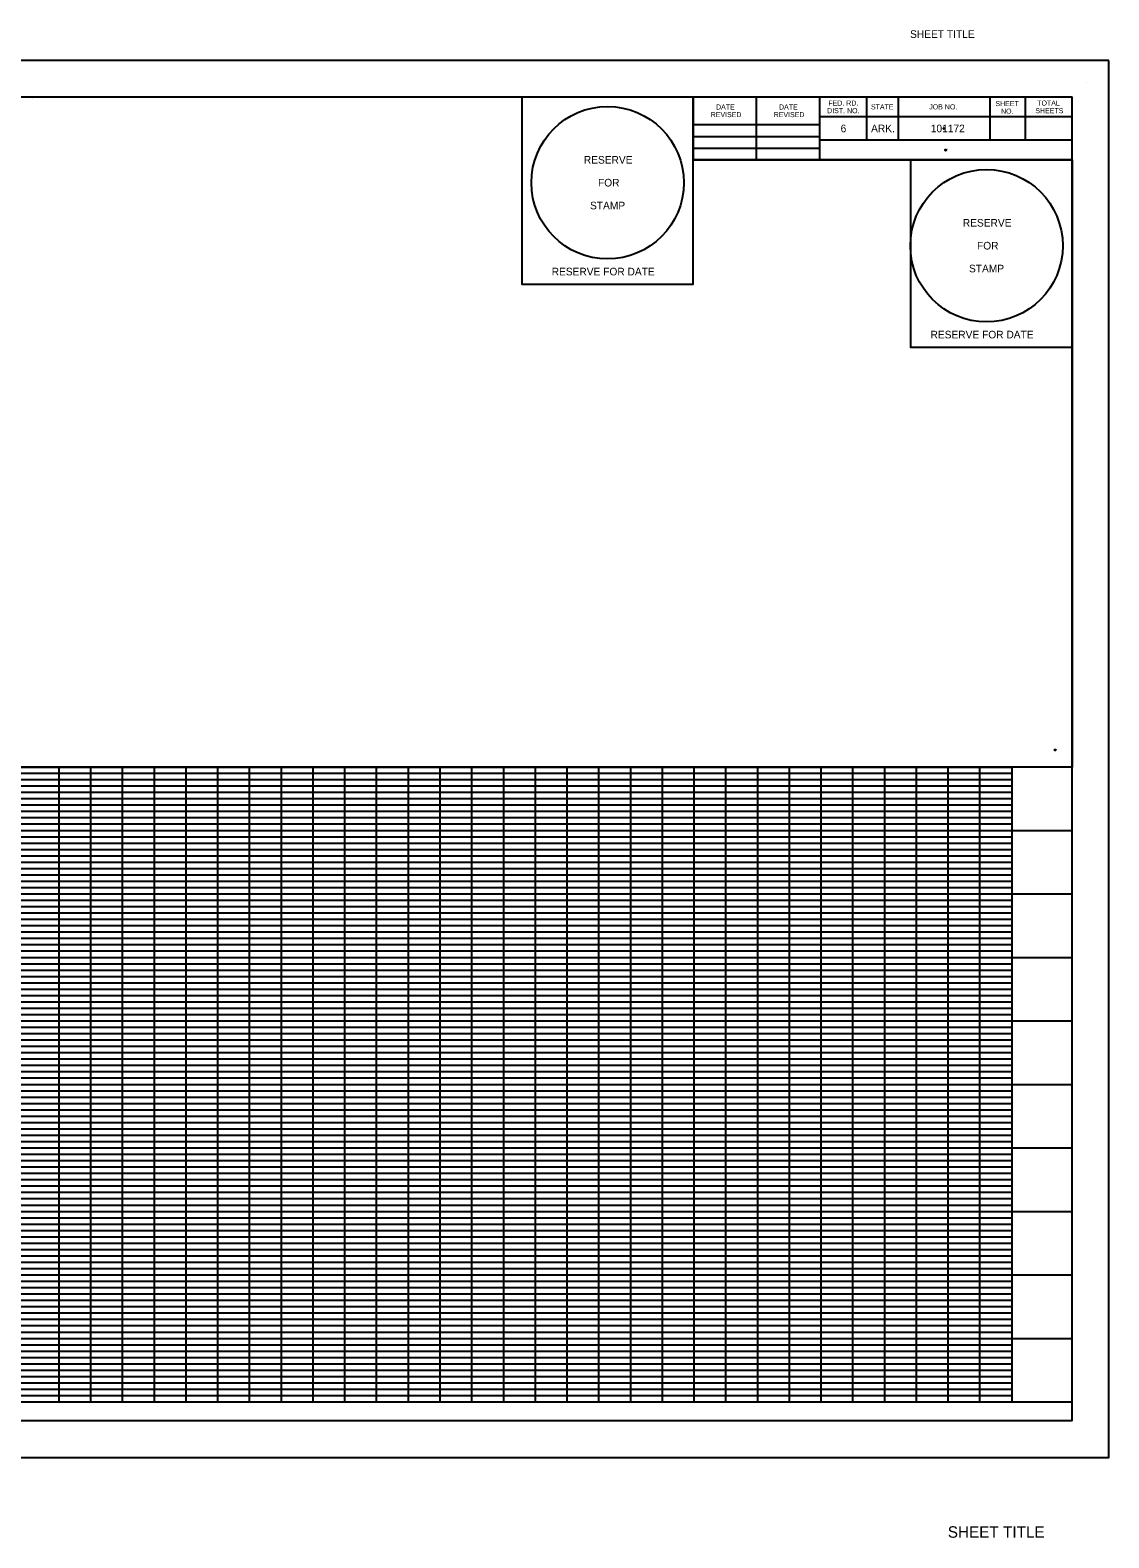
# Model space of a CAD drawing. Extents: x 0 to 17, y -0.6 to 11.2.
# Drawn here: x 8.51 to 17, y -0.63 to 11.24 of the extents above; entities that cross this region are included whole.
import ezdxf

# ---------------------------------------------------------------- set-up
doc = ezdxf.new("R2010")
doc.units = 0
for name, color, linetype in [('G-ANNO-TEXT', 7, 'Continuous'), ('G-Border-Paper', 7, 'Continuous'), ('G-Border-Sheet', 7, 'Continuous'), ('G-Grid-Border', 7, 'Continuous'), ('G-Grid-Major', 7, 'Continuous'), ('G-Grid-Minor', 7, 'Continuous'), ('G-No Plot-Anchor', 7, 'Continuous'), ('G-No Plot-Border-1', 7, 'Continuous'), ('G-No Plot-Border-2', 7, 'Continuous'), ('G-No Plot-Stamp-1', 7, 'Continuous'), ('G-No Plot-Stamp-2', 7, 'Continuous'), ('G-Table-Major', 7, 'Continuous'), ('G-Table-Minor', 7, 'Continuous')]:
    doc.layers.add(name, color=color, linetype=linetype)

msp = doc.modelspace()

# ---------------------------------------------------------------- linework, layer by layer
at = {"layer": 'G-ANNO-TEXT'}
msp.add_line((16.821, 10.827), (16.821, 10.827), dxfattribs=at)
at = {"layer": 'G-Border-Paper'}
msp.add_lwpolyline([(17, 11), (0, 11), (0, 0), (17, 0)], close=True, dxfattribs=at)
at = {"layer": 'G-Border-Sheet'}
for p, q in [((0.758, 10.712), (16.712, 10.712)), ((16.712, 0.288), (16.712, 10.712)), ((16.712, 0.288), (0.758, 0.288))]:
    msp.add_line(p, q, dxfattribs=at)
at = {"layer": 'G-Grid-Border'}
for p, q in [((16.712, 5.435), (0.758, 5.435)), ((16.712, 0.435), (0.758, 0.435))]:
    msp.add_line(p, q, dxfattribs=at)
msp.add_lwpolyline([(1.235, 5.435), (16.235, 5.435), (16.235, 0.435), (1.235, 0.435)], close=True, dxfattribs=at)
at = {"layer": 'G-Grid-Major'}
for p, q in [((8.735, 0.435), (8.735, 5.435)), ((9.235, 0.435), (9.235, 5.435)), ((9.735, 0.435), (9.735, 5.435)), ((10.235, 0.435), (10.235, 5.435)), ((10.735, 0.435), (10.735, 5.435)), ((11.235, 0.435), (11.235, 5.435)), ((11.735, 0.435), (11.735, 5.435)), ((12.235, 0.435), (12.235, 5.435)), ((12.735, 0.435), (12.735, 5.435)), ((13.235, 0.435), (13.235, 5.435)), ((13.735, 0.435), (13.735, 5.435)), ((14.235, 0.435), (14.235, 5.435)), ((14.735, 0.435), (14.735, 5.435)), ((15.235, 0.435), (15.235, 5.435)), ((15.735, 0.435), (15.735, 5.435)), ((16.712, 4.935), (0.758, 4.935)), ((16.712, 4.435), (0.758, 4.435)), ((16.712, 3.935), (0.758, 3.935)), ((16.712, 3.435), (0.758, 3.435)), ((16.712, 2.935), (0.758, 2.935)), ((16.712, 2.435), (0.758, 2.435)), ((16.712, 1.935), (0.758, 1.935)), ((16.712, 1.435), (0.758, 1.435)), ((16.712, 0.935), (0.758, 0.935))]:
    msp.add_line(p, q, dxfattribs=at)
msp.add_lwpolyline([(1.235, 5.435), (16.235, 5.435), (16.235, 0.435), (1.235, 0.435)], close=True, dxfattribs=at)
at = {"layer": 'G-Grid-Minor'}
for p, q in [((16.235, 5.385), (1.235, 5.385)), ((8.985, 0.435), (8.985, 5.435)), ((9.485, 0.435), (9.485, 5.435)), ((9.985, 0.435), (9.985, 5.435)), ((10.485, 0.435), (10.485, 5.435)), ((10.985, 0.435), (10.985, 5.435)), ((11.485, 0.435), (11.485, 5.435)), ((11.985, 0.435), (11.985, 5.435)), ((12.485, 0.435), (12.485, 5.435)), ((12.985, 0.435), (12.985, 5.435)), ((13.485, 0.435), (13.485, 5.435)), ((13.985, 0.435), (13.985, 5.435)), ((14.485, 0.435), (14.485, 5.435)), ((14.985, 0.435), (14.985, 5.435)), ((15.485, 0.435), (15.485, 5.435)), ((15.985, 0.435), (15.985, 5.435)), ((16.235, 5.335), (1.235, 5.335)), ((16.235, 5.285), (1.235, 5.285)), ((16.235, 5.235), (1.235, 5.235)), ((16.235, 5.185), (1.235, 5.185)), ((16.235, 5.135), (1.235, 5.135)), ((16.235, 5.085), (1.235, 5.085)), ((16.235, 5.035), (1.235, 5.035)), ((16.235, 4.985), (1.235, 4.985)), ((16.235, 4.885), (1.235, 4.885)), ((16.235, 4.835), (1.235, 4.835)), ((16.235, 4.785), (1.235, 4.785)), ((16.235, 4.735), (1.235, 4.735)), ((16.235, 4.685), (1.235, 4.685)), ((16.235, 4.635), (1.235, 4.635)), ((16.235, 4.585), (1.235, 4.585)), ((16.235, 4.535), (1.235, 4.535)), ((16.235, 4.485), (1.235, 4.485)), ((16.235, 4.385), (1.235, 4.385)), ((16.235, 4.335), (1.235, 4.335)), ((16.235, 4.285), (1.235, 4.285)), ((16.235, 4.235), (1.235, 4.235)), ((16.235, 4.185), (1.235, 4.185)), ((16.235, 4.135), (1.235, 4.135)), ((16.235, 4.085), (1.235, 4.085)), ((16.235, 4.035), (1.235, 4.035)), ((16.235, 3.985), (1.235, 3.985)), ((16.235, 3.885), (1.235, 3.885)), ((16.235, 3.835), (1.235, 3.835)), ((16.235, 3.785), (1.235, 3.785)), ((16.235, 3.735), (1.235, 3.735)), ((16.235, 3.685), (1.235, 3.685)), ((16.235, 3.635), (1.235, 3.635)), ((16.235, 3.585), (1.235, 3.585)), ((16.235, 3.535), (1.235, 3.535)), ((16.235, 3.485), (1.235, 3.485)), ((16.235, 3.385), (1.235, 3.385)), ((16.235, 3.335), (1.235, 3.335)), ((16.235, 3.285), (1.235, 3.285)), ((16.235, 3.235), (1.235, 3.235)), ((16.235, 3.185), (1.235, 3.185)), ((16.235, 3.135), (1.235, 3.135)), ((16.235, 3.085), (1.235, 3.085)), ((16.235, 3.035), (1.235, 3.035)), ((16.235, 2.985), (1.235, 2.985)), ((16.235, 2.885), (1.235, 2.885)), ((16.235, 2.835), (1.235, 2.835)), ((16.235, 2.785), (1.235, 2.785)), ((16.235, 2.735), (1.235, 2.735)), ((16.235, 2.685), (1.235, 2.685)), ((16.235, 2.635), (1.235, 2.635)), ((16.235, 2.585), (1.235, 2.585)), ((16.235, 2.535), (1.235, 2.535)), ((16.235, 2.485), (1.235, 2.485)), ((16.235, 2.385), (1.235, 2.385)), ((16.235, 2.335), (1.235, 2.335)), ((16.235, 2.285), (1.235, 2.285)), ((16.235, 2.235), (1.235, 2.235)), ((16.235, 2.185), (1.235, 2.185)), ((16.235, 2.135), (1.235, 2.135)), ((16.235, 2.085), (1.235, 2.085)), ((16.235, 2.035), (1.235, 2.035)), ((16.235, 1.985), (1.235, 1.985)), ((16.235, 1.885), (1.235, 1.885)), ((16.235, 1.835), (1.235, 1.835)), ((16.235, 1.785), (1.235, 1.785)), ((16.235, 1.735), (1.235, 1.735)), ((16.235, 1.685), (1.235, 1.685)), ((16.235, 1.635), (1.235, 1.635)), ((16.235, 1.585), (1.235, 1.585)), ((16.235, 1.535), (1.235, 1.535)), ((16.235, 1.485), (1.235, 1.485)), ((16.235, 1.385), (1.235, 1.385)), ((16.235, 1.335), (1.235, 1.335)), ((16.235, 1.285), (1.235, 1.285)), ((16.235, 1.235), (1.235, 1.235)), ((16.235, 1.185), (1.235, 1.185)), ((16.235, 1.135), (1.235, 1.135)), ((16.235, 1.085), (1.235, 1.085)), ((16.235, 1.035), (1.235, 1.035)), ((16.235, 0.985), (1.235, 0.985)), ((16.235, 0.885), (1.235, 0.885)), ((16.235, 0.835), (1.235, 0.835)), ((16.235, 0.785), (1.235, 0.785)), ((16.235, 0.735), (1.235, 0.735)), ((16.235, 0.685), (1.235, 0.685)), ((16.235, 0.635), (1.235, 0.635)), ((16.235, 0.585), (1.235, 0.585)), ((16.235, 0.535), (1.235, 0.535)), ((16.235, 0.485), (1.235, 0.485))]:
    msp.add_line(p, q, dxfattribs=at)
at = {"layer": 'G-No Plot-Anchor'}
for centre in [(15.701, 10.464), (15.716, 10.294), (16.577, 5.57)]:
    msp.add_circle(centre, 0.005, dxfattribs=at)
at = {"layer": 'G-No Plot-Border-1'}
msp.add_lwpolyline([(0.758, 5.435), (0.758, 10.712), (13.728, 10.712), (13.728, 10.216), (14.721, 10.216), (14.897, 10.216), (15.437, 10.216), (15.437, 8.741), (16.712, 8.741), (16.712, 5.435)], close=True, dxfattribs=at)
at = {"layer": 'G-No Plot-Border-2'}
msp.add_lwpolyline([(0.758, 5.435), (0.758, 10.712), (12.378, 10.712), (12.378, 9.237), (13.728, 9.237), (13.728, 10.216), (14.721, 10.216), (14.897, 10.216), (16.712, 10.216), (16.712, 5.435)], close=True, dxfattribs=at)
at = {"layer": 'G-No Plot-Stamp-1'}
msp.add_circle((16.037, 9.541), 0.6, dxfattribs=at)
at = {"layer": 'G-No Plot-Stamp-2'}
msp.add_circle((13.053, 10.037), 0.6, dxfattribs=at)
at = {"layer": 'G-Table-Major'}
for p, q in [((13.728, 10.217), (13.728, 10.712)), ((14.721, 10.712), (14.721, 10.216)), ((13.728, 10.495), (14.721, 10.495)), ((16.712, 10.216), (13.728, 10.216))]:
    msp.add_line(p, q, dxfattribs=at)
at = {"layer": 'G-Table-Minor'}
for p, q in [((8.529, 10.699), (8.529, 10.699)), ((8.529, 10.699), (8.529, 10.699)), ((14.226, 10.216), (14.226, 10.712)), ((15.093, 10.712), (15.093, 10.372)), ((15.341, 10.712), (15.341, 10.372)), ((16.062, 10.712), (16.062, 10.372)), ((16.34, 10.712), (16.34, 10.372)), ((16.712, 10.566), (16.712, 10.566)), ((16.712, 10.556), (14.721, 10.556)), ((13.728, 10.401), (14.721, 10.401)), ((16.712, 10.372), (14.721, 10.372)), ((13.728, 10.31), (14.721, 10.31))]:
    msp.add_line(p, q, dxfattribs=at)

# ---------------------------------------------------------------- texts
at = {"layer": 'G-ANNO-TEXT'}
for s, height, p in [('SHEET TITLE', 0.06, (15.435, 11.177)), ('TOTAL', 0.04, (16.436, 10.644)), ('REVISED', 0.04, (13.865, 10.553)), ('DATE', 0.04, (13.907, 10.613)), ('REVISED', 0.04, (14.361, 10.553)), ('DATE', 0.04, (14.403, 10.613)), ('DIST. NO.', 0.04, (14.782, 10.584)), ('FED. RD.', 0.04, (14.791, 10.644)), ('STATE', 0.04, (15.127, 10.614)), ('JOB NO.', 0.04, (15.586, 10.614)), ('SHEET', 0.04, (16.107, 10.64)), ('NO.', 0.04, (16.151, 10.58)), ('SHEETS', 0.04, (16.421, 10.584)), ('6', 0.06, (14.888, 10.434)), ('ARK.', 0.06, (15.128, 10.434)), ('101172', 0.06, (15.598, 10.434)), ('SHEET TITLE', 0.09, (15.732, -0.632))]:
    msp.add_text(s, height=height, dxfattribs=at).set_placement(p)
at = {"layer": 'G-No Plot-Stamp-1'}
for s, p in [('RESERVE', (15.85, 9.691)), ('FOR ', (15.962, 9.511)), ('STAMP', (15.899, 9.331)), ('RESERVE FOR DATE', (15.596, 8.811))]:
    msp.add_text(s, height=0.06, dxfattribs=at).set_placement(p)
at = {"layer": 'G-No Plot-Stamp-2'}
for s, p in [('RESERVE', (12.866, 10.187)), ('FOR ', (12.978, 10.007)), ('STAMP', (12.915, 9.827)), ('RESERVE FOR DATE', (12.613, 9.307))]:
    msp.add_text(s, height=0.06, dxfattribs=at).set_placement(p)

doc.saveas('drawing.dxf')
